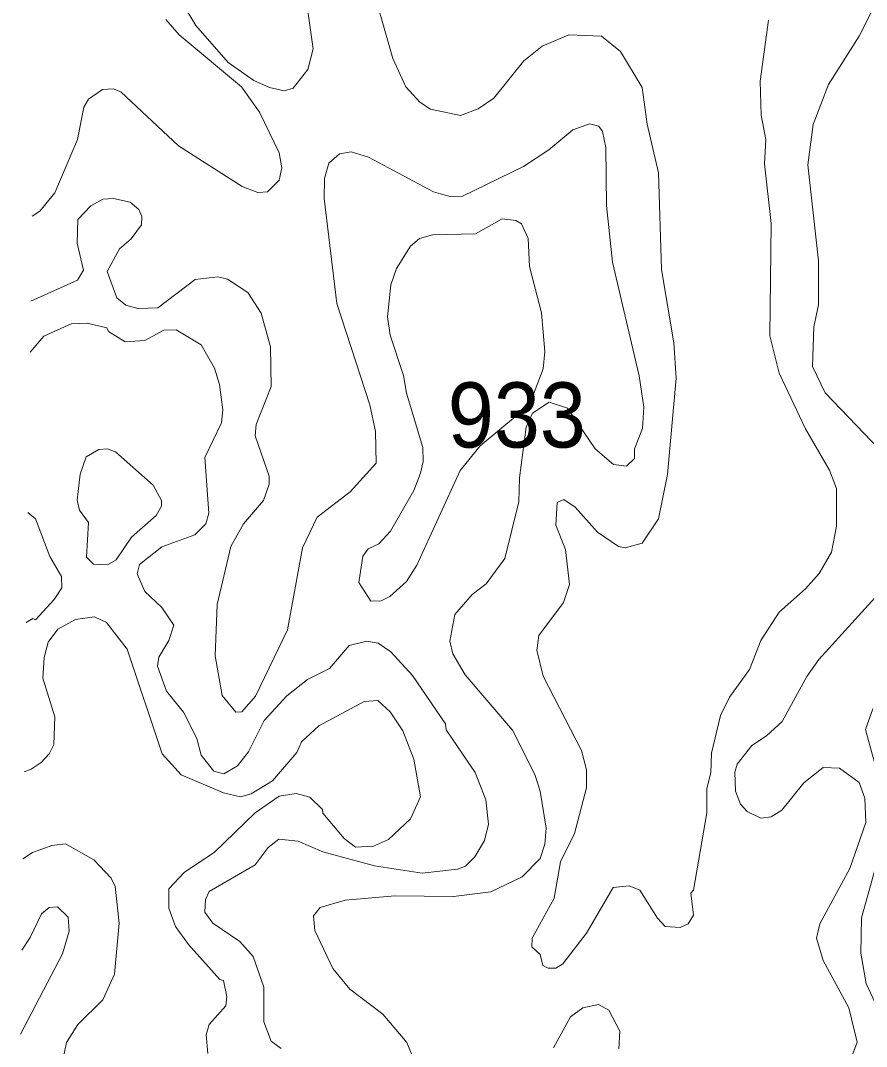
# Model space of a CAD drawing. Extents: x 763.2 to 816.8, y 7896.5 to 7952.7.
# Drawn here: x 763.516 to 765.593, y 7920.185 to 7922.705 of the extents above; entities that cross this region are included whole.
import ezdxf

# ---------------------------------------------------------------- set-up
doc = ezdxf.new("R2010")
doc.units = 0
doc.header["$LTSCALE"] = 0.064
doc.layers.add('2', color=7, linetype='Continuous', lineweight=13)
doc.layers.add('21', color=7, linetype='Continuous')

msp = doc.modelspace()

# ---------------------------------------------------------------- linework, layer by layer
at = {"layer": '2'}
for points in [[(764.3392, 7922.9305), (764.4304, 7922.6115), (764.4619, 7922.5419), (764.4963, 7922.504), (764.5224, 7922.487), (764.5967, 7922.4716), (764.6398, 7922.4879), (764.6784, 7922.5139), (764.7522, 7922.6054), (764.7971, 7922.642), (764.8622, 7922.6698), (764.943, 7922.6666), (764.9892, 7922.6288), (765.0428, 7922.5399), (765.0551, 7922.4499), (765.083, 7922.3308), (765.0897, 7922.0934), (765.1204, 7921.9132), (765.1258, 7921.8264), (765.1044, 7921.5901), (765.0829, 7921.481), (765.0422, 7921.4216), (765.0011, 7921.4098), (764.9842, 7921.4132), (764.9332, 7921.4479), (764.8778, 7921.5095), (764.8503, 7921.5288), (764.8335, 7921.5211), (764.8304, 7921.4654), (764.8543, 7921.406), (764.8644, 7921.3198), (764.8491, 7921.2756), (764.7888, 7921.1943), (764.7842, 7921.1589), (764.7992, 7921.0947), (764.8936, 7920.9122), (764.9055, 7920.8648), (764.9055, 7920.8203), (764.8761, 7920.7084), (764.8416, 7920.6387), (764.8263, 7920.5494), (764.7725, 7920.4514), (764.7717, 7920.4303), (764.7921, 7920.4112), (764.799, 7920.3842), (764.8116, 7920.3775), (764.8308, 7920.3779), (764.8476, 7920.3886), (764.9058, 7920.4635), (764.9713, 7920.5758), (765.0107, 7920.5794), (765.0368, 7920.5695), (765.0802, 7920.5003), (765.0991, 7920.4802), (765.1362, 7920.4777), (765.1554, 7920.4861), (765.1683, 7920.508), (765.162, 7920.5619), (765.1684, 7920.5691), (765.2011, 7920.7589), (765.2014, 7920.8188), (765.2109, 7920.8575), (765.213, 7920.9056), (765.2349, 7920.9984), (765.2573, 7921.043), (765.3062, 7921.1114), (765.3336, 7921.1824), (765.379, 7921.252), (765.4439, 7921.3088), (765.4769, 7921.3465), (765.5072, 7921.3988), (765.5201, 7921.463), (765.52, 7921.5556), (765.5026, 7921.6004), (765.4438, 7921.7018), (765.3786, 7921.8391), (765.3559, 7921.9305), (765.3591, 7922.2059), (765.3427, 7922.3531), (765.3459, 7922.4129), (765.3346, 7922.4722), (765.3326, 7922.5557), (765.3529, 7922.706)], [(763.9026, 7922.7668), (763.9462, 7922.6925), (764.0258, 7922.6016), (764.0893, 7922.5571), (764.1272, 7922.5399), (764.1636, 7922.5321), (764.1857, 7922.5389), (764.2217, 7922.5848), (764.235, 7922.6349), (764.2201, 7922.739)], [(765.6121, 7922.7389), (765.5756, 7922.6662), (765.5002, 7922.5478), (765.4628, 7922.4498), (765.4495, 7922.3505), (765.4757, 7922.1145), (765.4757, 7922.0068), (765.4643, 7921.9528), (765.4612, 7921.8549), (765.492, 7921.7907), (765.6828, 7921.5919)], [(763.5442, 7922.2242), (763.5635, 7922.2368), (763.6002, 7922.2816), (763.6559, 7922.4123), (763.6715, 7922.4923), (763.683, 7922.5118), (763.7171, 7922.5353), (763.7439, 7922.5369), (763.762, 7922.5299), (763.9041, 7922.3972), (764.0602, 7922.2973), (764.0989, 7922.2826), (764.1222, 7922.2843), (764.1513, 7922.3125), (764.1576, 7922.3433), (764.1513, 7922.3802), (764.1031, 7922.48), (764.0585, 7922.5422), (763.9053, 7922.6695), (763.8728, 7922.7075)], [(764.5779, 7921.1497), (764.5703, 7921.1805), (764.5829, 7921.2459), (764.6252, 7921.2952), (764.6594, 7921.3213), (764.7049, 7921.3839), (764.7394, 7921.5229), (764.7412, 7921.582), (764.7576, 7921.7062), (764.7735, 7921.7407), (764.8141, 7921.7676), (764.8594, 7921.753), (764.9269, 7921.653), (764.9719, 7921.6143), (765.0043, 7921.6104), (765.0237, 7921.6288), (765.0241, 7921.6528), (765.0433, 7921.7026), (765.0468, 7921.7553), (765.0351, 7921.8325), (764.9697, 7922.1112), (764.955, 7922.2504), (764.9532, 7922.3932), (764.9453, 7922.4319), (764.936, 7922.445), (764.9134, 7922.4514), (764.8721, 7922.4362), (764.8135, 7922.3874), (764.751, 7922.3463), (764.6017, 7922.2738), (764.5704, 7922.2724), (764.5302, 7922.2841), (764.3702, 7922.3689), (764.3277, 7922.3822), (764.2996, 7922.3775), (764.2729, 7922.3542), (764.2628, 7922.317), (764.2613, 7922.2676), (764.2925, 7922.01), (764.3735, 7921.7607), (764.388, 7921.6958), (764.3894, 7921.6177), (764.3258, 7921.5472), (764.2442, 7921.4849), (764.2087, 7921.4096), (764.1717, 7921.2085), (764.0932, 7921.0458), (764.0595, 7921.0067), (764.045, 7921.0061), (764.0108, 7921.0468), (763.9936, 7921.1443), (763.9987, 7921.2706), (764.0321, 7921.4134), (764.0632, 7921.4691), (764.1127, 7921.5257), (764.1265, 7921.5663), (764.1262, 7921.5856), (764.0921, 7921.6846), (764.0949, 7921.7123), (764.1314, 7921.8063), (764.1298, 7921.9036), (764.1068, 7921.9863), (764.0744, 7922.0365), (764.0243, 7922.0693), (764.0009, 7922.075), (763.9448, 7922.0684), (763.8531, 7921.9995), (763.8044, 7921.9979), (763.775, 7922.0058), (763.7527, 7922.0236), (763.7291, 7922.0882), (763.759, 7922.1439), (763.7877, 7922.1685), (763.8128, 7922.2029), (763.8141, 7922.2231), (763.8068, 7922.2403), (763.7851, 7922.2588), (763.7445, 7922.2673), (763.718, 7922.2658), (763.689, 7922.25), (763.6567, 7922.2158), (763.6549, 7922.1579), (763.671, 7922.0916), (763.656, 7922.0673), (763.5413, 7922.0155)], [(763.5395, 7921.8906), (763.5729, 7921.9298), (763.6402, 7921.9599), (763.6795, 7921.9616), (763.7278, 7921.9504), (763.7324, 7921.9408), (763.773, 7921.9157), (763.8213, 7921.9191), (763.8679, 7921.9444), (763.8979, 7921.945), (763.9592, 7921.9086), (763.992, 7921.851), (764.0044, 7921.8113), (764.013, 7921.7491), (764.0096, 7921.717), (763.969, 7921.632), (763.9786, 7921.4948), (763.9707, 7921.4685), (763.9442, 7921.4417), (763.863, 7921.4123), (763.8082, 7921.3686), (763.8027, 7921.3463), (763.8209, 7921.3028), (763.8629, 7921.2636), (763.8927, 7921.22), (763.8804, 7921.1825), (763.8553, 7921.1409), (763.8522, 7921.1188), (763.8741, 7921.0579), (763.9164, 7921.0061), (763.9488, 7920.9418), (763.9597, 7920.9005), (763.9905, 7920.8617), (764.0151, 7920.8544), (764.0485, 7920.8746), (764.0759, 7920.9088), (764.1142, 7920.9859), (764.1698, 7921.0467), (764.2206, 7921.0865), (764.2744, 7921.1137), (764.323, 7921.17), (764.3664, 7921.181), (764.3943, 7921.1759), (764.4256, 7921.1547), (764.4786, 7921.0966), (764.5598, 7920.9777), (764.5613, 7920.9628), (764.6323, 7920.8578), (764.6584, 7920.7913), (764.6655, 7920.7314), (764.6554, 7920.6907), (764.6316, 7920.6509), (764.6083, 7920.6278), (764.5893, 7920.6207), (764.502, 7920.6108), (764.3851, 7920.629), (764.258, 7920.6634), (764.1982, 7920.6898), (764.1507, 7920.6946), (764.1243, 7920.6743), (764.0924, 7920.6312), (763.979, 7920.5662), (763.9704, 7920.5459), (763.969, 7920.5155), (763.9884, 7920.4877), (764.0542, 7920.4431), (764.087, 7920.4063), (764.1131, 7920.3312), (764.1132, 7920.2457), (764.1318, 7920.1984), (764.1562, 7920.1803)], [(763.5302, 7921.2264), (763.5461, 7921.2366), (763.5524, 7921.2333), (763.5988, 7921.2832), (763.6171, 7921.3118), (763.6167, 7921.3391), (763.5876, 7921.3888), (763.5531, 7921.4812), (763.534, 7921.4968)], [(765.6545, 7921.3317), (765.4766, 7921.1354), (765.4466, 7921.0942), (765.3862, 7920.9833), (765.3481, 7920.9482), (765.3115, 7920.9246), (765.2754, 7920.8787), (765.2704, 7920.8587), (765.2721, 7920.8121), (765.2836, 7920.7802), (765.3001, 7920.7619), (765.3341, 7920.7456), (765.3591, 7920.7491), (765.3859, 7920.7657), (765.4397, 7920.8326), (765.4868, 7920.87), (765.5271, 7920.8684), (765.5758, 7920.8339), (765.5891, 7920.795), (765.5917, 7920.7351), (765.5528, 7920.6224), (765.4784, 7920.4863), (765.471, 7920.4514), (765.487, 7920.3962), (765.5499, 7920.2798), (765.5707, 7920.1962), (765.5572, 7920.1608)], [(763.9756, 7920.1681), (763.9722, 7920.2139), (763.9792, 7920.2389), (764.0198, 7920.2854), (764.0227, 7920.3075), (764.0145, 7920.347), (764.0053, 7920.3499), (763.9288, 7920.4355), (763.8968, 7920.4803), (763.8805, 7920.5247), (763.8802, 7920.5721), (763.9187, 7920.6137), (763.9912, 7920.6613), (764.0918, 7920.7587), (764.1512, 7920.7996), (764.1929, 7920.8062), (764.2266, 7920.7979), (764.2573, 7920.7672), (764.2586, 7920.7585), (764.311, 7920.696), (764.3385, 7920.675), (764.3827, 7920.6768), (764.4195, 7920.6935), (764.4736, 7920.7446), (764.4978, 7920.798), (764.4817, 7920.8911), (764.4551, 7920.9608), (764.4239, 7921.0068), (764.3935, 7921.0345), (764.3596, 7921.0327), (764.2482, 7920.9723), (764.206, 7920.9332), (764.1944, 7920.9068), (764.1347, 7920.8378), (764.0824, 7920.8058), (764.0565, 7920.7981), (764.0141, 7920.8083), (763.9105, 7920.8524), (763.8636, 7920.9043), (763.7781, 7921.1606), (763.7269, 7921.2268), (763.6973, 7921.2401), (763.6507, 7921.2337), (763.6077, 7921.2104)], [(763.6077, 7921.2104), (763.584, 7921.1784), (763.5741, 7921.1401), (763.5711, 7921.0897), (763.6004, 7920.9944), (763.5979, 7920.9272)], [(764.8069, 7920.721), (764.7922, 7920.8123), (764.7787, 7920.8531), (764.7239, 7920.962), (764.6077, 7921.0979), (764.5779, 7921.1497)], [(765.627, 7920.832), (765.5911, 7920.9634), (765.6087, 7921.0141)], [(763.5979, 7920.9272), (763.586, 7920.9038), (763.5671, 7920.8823), (763.5421, 7920.866), (763.525, 7920.8595)], [(764.4831, 7920.149), (764.4649, 7920.195), (764.4053, 7920.2644), (764.3243, 7920.326), (764.2828, 7920.3766), (764.2391, 7920.4698), (764.2355, 7920.5059), (764.2515, 7920.5266), (764.3133, 7920.5448), (764.4349, 7920.5548), (764.5793, 7920.5534), (764.6712, 7920.5654), (764.7481, 7920.6017), (764.7921, 7920.6469), (764.8037, 7920.6821), (764.8069, 7920.721)], [(763.522, 7920.6464), (763.5458, 7920.6619), (763.5932, 7920.6787), (763.6268, 7920.683), (763.6959, 7920.6435), (763.739, 7920.5988), (763.7486, 7920.5781), (763.7584, 7920.4877), (763.7467, 7920.3627), (763.7184, 7920.2997), (763.6564, 7920.239), (763.6286, 7920.195), (763.6155, 7920.1318)], [(765.6255, 7920.2699), (765.5923, 7920.3403), (765.5793, 7920.4142), (765.5812, 7920.5014), (765.619, 7920.6361)], [(763.516, 7920.2156), (763.6191, 7920.4127), (763.6351, 7920.4685), (763.633, 7920.5026), (763.607, 7920.5282), (763.5864, 7920.5266), (763.5675, 7920.5114), (763.5398, 7920.4529), (763.5189, 7920.4216)], [(764.9855, 7920.1793), (764.9874, 7920.2227), (764.9606, 7920.2742), (764.935, 7920.2885), (764.8965, 7920.2804), (764.8667, 7920.2578), (764.8251, 7920.1822)]]:
    msp.add_lwpolyline(points, dxfattribs=at)
for points in [[(764.8034, 7921.8917), (764.7951, 7921.987), (764.766, 7922.1007), (764.7626, 7922.1697), (764.7465, 7922.2056), (764.732, 7922.2137), (764.6987, 7922.2178), (764.6329, 7922.1805), (764.5275, 7922.1786), (764.4958, 7922.1691), (764.4736, 7922.1506), (764.4392, 7922.0954), (764.4257, 7922.0554), (764.4175, 7921.9772), (764.4237, 7921.932), (764.4568, 7921.833), (764.4641, 7921.79), (764.5041, 7921.6559), (764.505, 7921.6218), (764.4984, 7921.5931), (764.4819, 7921.5509), (764.4246, 7921.4505), (764.3955, 7921.4195), (764.37, 7921.4074), (764.3563, 7921.3893), (764.3469, 7921.3247), (764.3762, 7921.2786), (764.4018, 7921.2797), (764.4227, 7921.2899), (764.4642, 7921.3269), (764.4889, 7921.3672), (764.596, 7921.5997), (764.645, 7921.6605), (764.7362, 7921.7366), (764.7736, 7921.7804), (764.7997, 7921.8495)], [(763.661, 7921.5027), (763.6549, 7921.5269), (763.6621, 7921.5909), (763.677, 7921.6333), (763.7082, 7921.6509), (763.7288, 7921.6526), (763.7489, 7921.6455), (763.8421, 7921.5639), (763.8618, 7921.5262), (763.8618, 7921.5121), (763.8488, 7921.4889), (763.7885, 7921.4363), (763.7506, 7921.3803), (763.7298, 7921.368), (763.6949, 7921.3694), (763.6782, 7921.3866), (763.6828, 7921.4724)]]:
    msp.add_lwpolyline(points, close=True, dxfattribs=at)

# ---------------------------------------------------------------- texts
at = {"layer": '21', "width": 0.95}
msp.add_text('933', height=0.16, dxfattribs=at).set_placement((764.5652, 7921.6561))

doc.saveas('drawing.dxf')
